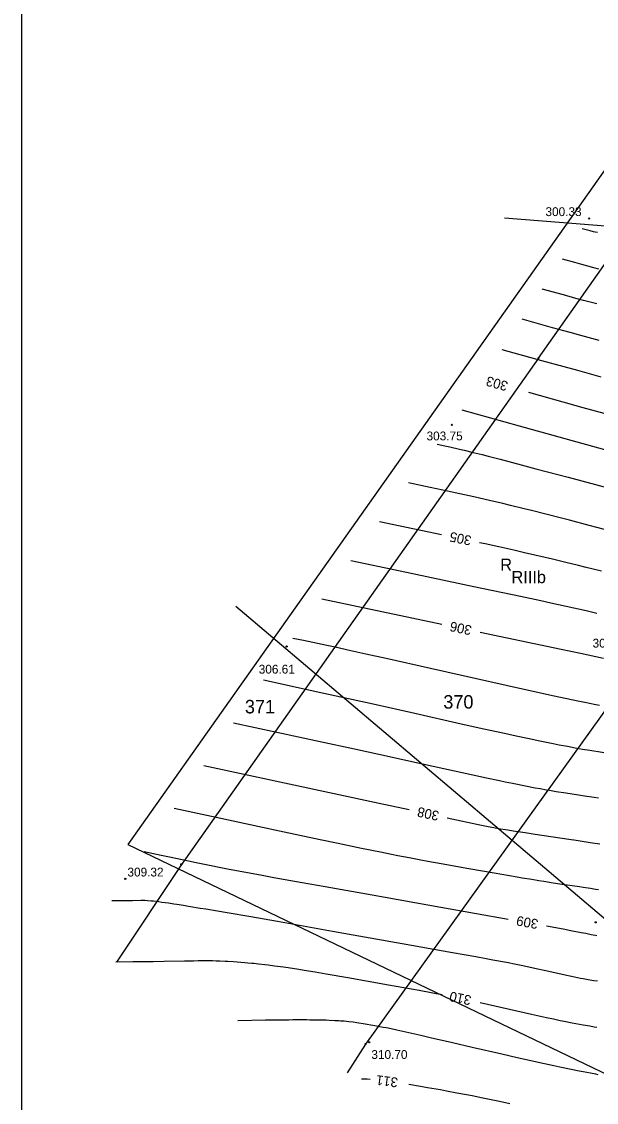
# Model space of a CAD drawing. Extents: x 7477803 to 7478145, y 5500698 to 5500984.
# Drawn here: x 7477803.3 to 7477847.5, y 5500809.5 to 5500892.7 of the extents above; entities that cross this region are included whole.
import ezdxf

# ---------------------------------------------------------------- set-up
doc = ezdxf.new("R2010")
doc.units = 0
for name, color, linetype in [('203-Punkt załamania granicy działki nie stabilizowany', 7, 'Continuous'), ('gr_dzialki', 7, 'Continuous'), ('gr_klasy', 7, 'Continuous'), ('nr_dzialki', 7, 'Continuous'), ('opis_klasy', 7, 'Continuous'), ('opis_uzytek', 7, 'Continuous'), ('pkt_wys', 7, 'Continuous'), ('robocza11', 7, 'Continuous'), ('warst_ciagla', 7, 'Continuous'), ('warst_opis', 7, 'Continuous'), ('warst_pogrub', 7, 'Continuous'), ('warst_przeryw', 7, 'Continuous'), ('zakresy', 7, 'Continuous')]:
    doc.layers.add(name, color=color, linetype=linetype)

# ---------------------------------------------------------------- blocks, each defined once
blk = doc.blocks.new('203')
blk.add_circle((0, 0), 0.045)
blk = doc.blocks.new('801_3')
at = {"layer": 'pkt_wys'}
blk.add_circle((0, 0), 0.045, dxfattribs=at)
blk.add_circle((0, 0), 0.045, dxfattribs=at)

msp = doc.modelspace()

# ---------------------------------------------------------------- linework, layer by layer
at = {"layer": 'gr_dzialki'}
for points in [[(7477843.04, 5500866.8), (7477880.41, 5500919.86)], [(7477843.04, 5500866.8), (7477815.55, 5500827.8)], [(7477867.48, 5500866.57), (7477829.72, 5500813.95)], [(7477815.55, 5500827.8), (7477810.57, 5500820.265)], [(7477829.72, 5500813.95), (7477828.305, 5500811.73)]]:
    msp.add_lwpolyline(points, dxfattribs=at)
at = {"layer": 'gr_klasy'}
for points in [[(7477840.435, 5500877.607), (7477896.14, 5500873.19)], [(7477856.78, 5500816.29), (7477819.732, 5500847.674)]]:
    msp.add_lwpolyline(points, dxfattribs=at)
at = {"layer": 'robocza11'}
msp.add_lwpolyline([(7478014.996, 5500697.565), (7478144.729, 5500697.565), (7478144.729, 5500983.565), (7477803.256, 5500983.565), (7477803.256, 5500697.565), (7478010.821, 5500697.565)], close=True, dxfattribs=at)
at = {"layer": 'warst_ciagla'}
for points in [[(7477844.866, 5500874.453), (7477845.811, 5500874.191), (7477846.358, 5500874.041), (7477847.277, 5500873.794), (7477847.658, 5500873.695)], [(7477847.722, 5500868.17), (7477846.288, 5500868.557), (7477845.475, 5500868.779), (7477844.123, 5500869.151), (7477841.774, 5500869.804)], [(7477849.051, 5500862.271), (7477846.483, 5500862.98), (7477844.946, 5500863.406), (7477842.289, 5500864.147)], [(7477835.253, 5500860.174), (7477835.837, 5500860.049), (7477836.215, 5500859.965), (7477836.949, 5500859.797), (7477837.307, 5500859.712), (7477838.01, 5500859.541), (7477838.701, 5500859.368), (7477839.16, 5500859.251), (7477840.083, 5500859.011), (7477841.696, 5500858.589), (7477842.834, 5500858.288), (7477845.333, 5500857.624), (7477847.433, 5500857.063), (7477851.692, 5500855.922)], [(7477835.604, 5500846.287), (7477826.364, 5500848.227)], [(7477848.041, 5500843.664), (7477846.268, 5500844.041), (7477844.795, 5500844.353), (7477838.54, 5500845.67)], [(7477821.865, 5500842.007), (7477825, 5500841.33), (7477826.512, 5500841), (7477828.785, 5500840.498), (7477830.32, 5500840.156), (7477833.526, 5500839.439), (7477837.092, 5500838.64), (7477838.836, 5500838.253), (7477840.437, 5500837.901), (7477841.096, 5500837.758), (7477841.927, 5500837.58), (7477842.321, 5500837.496), (7477843.155, 5500837.32), (7477844.16, 5500837.113), (7477844.621, 5500837.021), (7477845.266, 5500836.895), (7477845.864, 5500836.784), (7477846.147, 5500836.734), (7477846.422, 5500836.687), (7477846.995, 5500836.591), (7477847.943, 5500836.433), (7477848.56, 5500836.328), (7477849.745, 5500836.12)], [(7477833.081, 5500832.002), (7477830.776, 5500832.499), (7477817.282, 5500835.4)], [(7477847.762, 5500829.344), (7477847.013, 5500829.467), (7477845.947, 5500829.634), (7477845.384, 5500829.719), (7477842.789, 5500830.101), (7477842.012, 5500830.218), (7477841.089, 5500830.36), (7477840.677, 5500830.426), (7477839.944, 5500830.549), (7477839.615, 5500830.607), (7477839.157, 5500830.693), (7477838.658, 5500830.796), (7477836.014, 5500831.369)], [(7477812.699, 5500828.794), (7477813.993, 5500828.517), (7477814.763, 5500828.353), (7477816.105, 5500828.072), (7477816.69, 5500827.951), (7477817.715, 5500827.743), (7477818.589, 5500827.569), (7477819.111, 5500827.468), (7477820.071, 5500827.285), (7477821.632, 5500826.993), (7477822.676, 5500826.8), (7477824.855, 5500826.404), (7477826.616, 5500826.087), (7477830.246, 5500825.44), (7477835.521, 5500824.503), (7477840.716, 5500823.582)], [(7477843.67, 5500823.056), (7477844.928, 5500822.827), (7477845.533, 5500822.715), (7477846.331, 5500822.562), (7477846.69, 5500822.49), (7477846.982, 5500822.428), (7477847.089, 5500822.406), (7477847.239, 5500822.376), (7477847.429, 5500822.344), (7477847.519, 5500822.331)], [(7477829.416, 5500811.282), (7477829.599, 5500811.28), (7477829.695, 5500811.277), (7477829.846, 5500811.269), (7477830.093, 5500811.25)], [(7477833.068, 5500810.866), (7477833.961, 5500810.713), (7477834.508, 5500810.618), (7477835.499, 5500810.442), (7477835.948, 5500810.361), (7477836.767, 5500810.209), (7477837.496, 5500810.07), (7477837.942, 5500809.982), (7477838.767, 5500809.817), (7477840.042, 5500809.555), (7477840.842, 5500809.385)]]:
    msp.add_lwpolyline(points, dxfattribs=at)
at = {"layer": 'warst_pogrub'}
for points in [[(7477835.571, 5500853.2), (7477830.809, 5500854.2)], [(7477847.883, 5500850.386), (7477846.721, 5500850.68), (7477846.115, 5500850.831), (7477845.155, 5500851.065), (7477844.114, 5500851.314), (7477843.555, 5500851.445), (7477841.959, 5500851.815), (7477841.146, 5500852.001), (7477839.977, 5500852.264), (7477838.945, 5500852.49), (7477838.507, 5500852.584)], [(7477810.503, 5500820.297), (7477811.819, 5500820.306), (7477812.45, 5500820.312), (7477813.374, 5500820.323), (7477814.236, 5500820.336), (7477815.797, 5500820.365), (7477816.485, 5500820.379), (7477816.836, 5500820.384), (7477817.375, 5500820.388), (7477817.746, 5500820.386), (7477817.935, 5500820.383), (7477818.224, 5500820.376), (7477818.519, 5500820.367), (7477818.924, 5500820.349), (7477819.131, 5500820.338), (7477819.553, 5500820.312), (7477820.136, 5500820.269), (7477820.435, 5500820.243), (7477820.663, 5500820.222), (7477820.972, 5500820.192), (7477821.129, 5500820.176), (7477821.486, 5500820.138), (7477821.972, 5500820.083), (7477822.22, 5500820.053), (7477822.725, 5500819.988), (7477823.417, 5500819.894), (7477823.771, 5500819.843), (7477824.587, 5500819.719), (7477825.005, 5500819.653), (7477825.854, 5500819.512), (7477826.706, 5500819.366), (7477828.36, 5500819.074), (7477831.492, 5500818.517), (7477833.86, 5500818.097), (7477834.774, 5500817.934), (7477835.166, 5500817.862), (7477835.49, 5500817.8), (7477835.62, 5500817.774)], [(7477838.553, 5500817.145), (7477842.496, 5500816.257), (7477843.655, 5500816.001), (7477844.193, 5500815.886), (7477844.7, 5500815.779), (7477845.022, 5500815.714), (7477845.631, 5500815.593), (7477845.919, 5500815.538), (7477846.468, 5500815.437), (7477846.985, 5500815.348), (7477847.315, 5500815.294), (7477847.53, 5500815.26)]]:
    msp.add_lwpolyline(points, dxfattribs=at)
at = {"layer": 'warst_przeryw'}
for points in [[(7477847.593, 5500876.475), (7477847.406, 5500876.515), (7477847.28, 5500876.545), (7477847.023, 5500876.611), (7477846.411, 5500876.778)], [(7477847.53, 5500870.978), (7477846.504, 5500871.252), (7477845.927, 5500871.409), (7477844.971, 5500871.67), (7477843.32, 5500872.129)], [(7477840.229, 5500867.479), (7477843.269, 5500866.632), (7477845.003, 5500866.152), (7477846.041, 5500865.866), (7477847.852, 5500865.37)], [(7477837.137, 5500862.829), (7477841.559, 5500861.595), (7477848.113, 5500859.77)], [(7477848.128, 5500853.602), (7477846.948, 5500853.914), (7477845.44, 5500854.308), (7477844.705, 5500854.498), (7477843.608, 5500854.778), (7477843.608, 5500854.778), (7477842.5, 5500855.057), (7477841.935, 5500855.197), (7477840.882, 5500855.455), (7477840.294, 5500855.596), (7477839.282, 5500855.831), (7477838.054, 5500856.108), (7477837.339, 5500856.266), (7477835.665, 5500856.628), (7477834.69, 5500856.837), (7477833.031, 5500857.187)], [(7477828.586, 5500851.214), (7477832.388, 5500850.415), (7477838.054, 5500849.22), (7477841.658, 5500848.455), (7477843.224, 5500848.119), (7477844.003, 5500847.951), (7477845.175, 5500847.693), (7477846.702, 5500847.352), (7477847.525, 5500847.164)], [(7477824.142, 5500845.24), (7477824.959, 5500845.068), (7477826.394, 5500844.763), (7477827.621, 5500844.497), (7477828.36, 5500844.335), (7477829.746, 5500844.029), (7477831.305, 5500843.682), (7477834.717, 5500842.918), (7477840.555, 5500841.61), (7477842.28, 5500841.226), (7477844.253, 5500840.792), (7477845.099, 5500840.608), (7477846.193, 5500840.374), (7477846.611, 5500840.285), (7477847.104, 5500840.183), (7477847.323, 5500840.138), (7477847.748, 5500840.053)], [(7477819.574, 5500838.703), (7477826.228, 5500837.271), (7477828.888, 5500836.697), (7477831.798, 5500836.063), (7477833.279, 5500835.738), (7477835.757, 5500835.19), (7477837.98, 5500834.695), (7477839.03, 5500834.465), (7477840.036, 5500834.252), (7477840.469, 5500834.162), (7477841.033, 5500834.047), (7477841.309, 5500833.992), (7477841.916, 5500833.873), (7477842.791, 5500833.708), (7477843.165, 5500833.64), (7477843.651, 5500833.554), (7477843.889, 5500833.513), (7477844.408, 5500833.426), (7477845.155, 5500833.308), (7477846.116, 5500833.162), (7477846.595, 5500833.088), (7477847.326, 5500832.972), (7477847.655, 5500832.917)], [(7477847.67, 5500825.829), (7477847.432, 5500825.868), (7477847.049, 5500825.929), (7477846.488, 5500826.016), (7477846.186, 5500826.061), (7477844.687, 5500826.282), (7477844.159, 5500826.362), (7477843.442, 5500826.474), (7477843.079, 5500826.533), (7477842.526, 5500826.623), (7477841.777, 5500826.748), (7477841.397, 5500826.813), (7477840.819, 5500826.913), (7477839.623, 5500827.124), (7477837.681, 5500827.468), (7477835.55, 5500827.847), (7477834.531, 5500828.029), (7477833.986, 5500828.128), (7477833.097, 5500828.294), (7477832.209, 5500828.465), (7477831.714, 5500828.563), (7477830.889, 5500828.727), (7477829.419, 5500829.026), (7477828.329, 5500829.251), (7477827.622, 5500829.398), (7477826.232, 5500829.691), (7477823.096, 5500830.358), (7477818.233, 5500831.4), (7477814.991, 5500832.097)], [(7477847.574, 5500818.794), (7477847.296, 5500818.836), (7477847.155, 5500818.859), (7477846.867, 5500818.908), (7477846.475, 5500818.978), (7477846.274, 5500819.016), (7477845.814, 5500819.107), (7477845.578, 5500819.156), (7477845.099, 5500819.259), (7477843.613, 5500819.591), (7477842.858, 5500819.756), (7477841.844, 5500819.971), (7477841.335, 5500820.076), (7477840.567, 5500820.23), (7477839.536, 5500820.429), (7477839.018, 5500820.527), (7477838.227, 5500820.671), (7477836.417, 5500820.994), (7477832.554, 5500821.68), (7477827.184, 5500822.634), (7477822.944, 5500823.387), (7477820.906, 5500823.745), (7477819.077, 5500824.061), (7477818.338, 5500824.187), (7477817.424, 5500824.34), (7477816.998, 5500824.411), (7477816.113, 5500824.556), (7477815.71, 5500824.62), (7477815.211, 5500824.698), (7477814.979, 5500824.734), (7477814.55, 5500824.799), (7477814.048, 5500824.871), (7477813.828, 5500824.901), (7477813.406, 5500824.954), (7477813.234, 5500824.972), (7477812.954, 5500824.997), (7477812.744, 5500825.008), (7477812.631, 5500825.01), (7477812.441, 5500825.008), (7477811.799, 5500824.997), (7477811.04, 5500824.99), (7477810.201, 5500824.986)], [(7477847.634, 5500811.594), (7477847.458, 5500811.626), (7477847.049, 5500811.703), (7477846.476, 5500811.813), (7477846.178, 5500811.871), (7477845.558, 5500811.996), (7477844.683, 5500812.177), (7477844.225, 5500812.275), (7477843.143, 5500812.51), (7477842.576, 5500812.635), (7477841.408, 5500812.898), (7477840.222, 5500813.168), (7477837.938, 5500813.695), (7477836.421, 5500814.045), (7477834.706, 5500814.438), (7477833.981, 5500814.604), (7477833.058, 5500814.814), (7477832.136, 5500815.021), (7477831.806, 5500815.094), (7477831.465, 5500815.166), (7477831.31, 5500815.198), (7477831.075, 5500815.241), (7477830.431, 5500815.355), (7477829.536, 5500815.514), (7477829.219, 5500815.569), (7477829.047, 5500815.597), (7477828.764, 5500815.638), (7477828.444, 5500815.676), (7477828.269, 5500815.694), (7477828.081, 5500815.71), (7477827.812, 5500815.73), (7477827.669, 5500815.739), (7477827.368, 5500815.756), (7477826.933, 5500815.775), (7477826.701, 5500815.783), (7477826.144, 5500815.797), (7477825.848, 5500815.802), (7477825.434, 5500815.807), (7477825.218, 5500815.809), (7477824.772, 5500815.811), (7477824.144, 5500815.809), (7477823.815, 5500815.807), (7477823.041, 5500815.799), (7477822.037, 5500815.783), (7477819.906, 5500815.738)]]:
    msp.add_lwpolyline(points, dxfattribs=at)
at = {"layer": 'zakresy'}
msp.add_lwpolyline([(7477995.059, 5500962.348), (7477983.951, 5500968.084), (7477970.781, 5500968.613), (7477936.09, 5500958.171), (7477930.511, 5500954.336), (7477914.305, 5500958.58), (7477904.32, 5500957.41), (7477897.265, 5500950.868), (7477811.424, 5500829.338), (7477936.003, 5500769.492), (7478008.982, 5500726.585), (7478019.402, 5500721.781), (7478037.95, 5500734.97), (7478039.493, 5500755.094), (7478043.98, 5500765.708), (7478067.545, 5500795.068), (7478092.109, 5500820.25), (7478076.156, 5500837.989), (7478068.105, 5500851.146), (7478061.422, 5500873.298), (7478054.135, 5500876.371), (7478039.669, 5500897.644), (7478026.36, 5500915.23), (7478015.054, 5500927.728)], close=True, dxfattribs=at)

# ---------------------------------------------------------------- block references
at = {"layer": '203-Punkt załamania granicy działki nie stabilizowany'}
for p in [(7477843.04, 5500866.8), (7477815.55, 5500827.8), (7477829.72, 5500813.95)]:
    msp.add_blockref('203', p, dxfattribs=at)
at = {"layer": 'pkt_wys', "rotation": 0.0626175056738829}
for p in [(7477846.937, 5500877.569), (7477836.364, 5500861.667), (7477823.653, 5500844.583), (7477811.233, 5500826.68), (7477847.446, 5500823.329), (7477830.006, 5500814.09)]:
    msp.add_blockref('801_3', p, dxfattribs=at)

# ---------------------------------------------------------------- texts
at = {"layer": 'nr_dzialki'}
for s, p in [('370', (7477835.715, 5500839.8)), ('371', (7477820.442, 5500839.432))]:
    msp.add_text(s, height=1.04, dxfattribs=at).set_placement(p)
at = {"layer": 'opis_klasy'}
msp.add_text('RIIIb', height=0.94, dxfattribs=at).set_placement((7477840.962, 5500849.465))
at = {"layer": 'opis_uzytek'}
msp.add_text('R', height=0.94, dxfattribs=at).set_placement((7477840.1, 5500850.42))
at = {"layer": 'pkt_wys'}
for s, p in [('300.33', (7477843.578, 5500877.749)), ('303.75', (7477834.424, 5500860.467)), ('305.94', (7477847.203, 5500844.502)), ('306.61', (7477821.506, 5500842.498)), ('309.32', (7477811.401, 5500826.864)), ('310.70', (7477830.177, 5500812.809))]:
    msp.add_text(s, height=0.68, rotation=0.06262, dxfattribs=at).set_placement(p)
at = {"layer": 'warst_opis'}
for s, rotation, p in [('303', 164.38977, (7477840.749, 5500864.973)), ('305', 168.13969, (7477837.934, 5500853.087)), ('306', 168.13969, (7477837.952, 5500846.177)), ('308', 167.82325, (7477835.443, 5500831.876)), ('309', 169.90794, (7477843.066, 5500823.544)), ('310', 167.8996, (7477837.922, 5500817.664)), ('311', 172.63675, (7477832.258, 5500811.349))]:
    msp.add_text(s, height=0.75, rotation=rotation, dxfattribs=at).set_placement(p)

doc.saveas('drawing.dxf')
